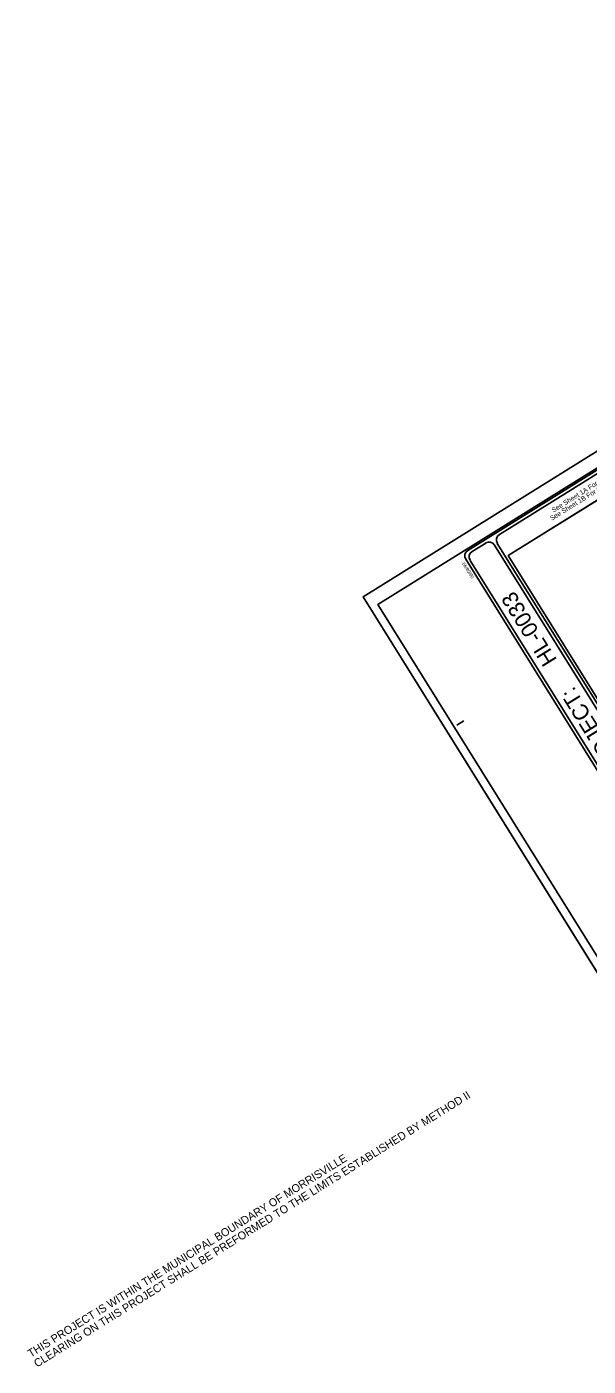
# Model space of a CAD drawing. Extents: x 2038094 to 2053858, y 751760 to 764312.
# Drawn here: x 2038094 to 2043353, y 751760 to 764312 of the extents above; entities that cross this region are included whole.
import ezdxf

# ---------------------------------------------------------------- set-up
doc = ezdxf.new("R2010")
doc.units = 0
for name, color, linetype in [('Sheet Clip Boundary CELL', 7, 'Continuous'), ('Sheet Cutting Line CELL', 7, 'Continuous'), ('Sheet Data Field CELL', 7, 'Continuous'), ('Sheet Plot Border Inside CELL', 7, 'Continuous'), ('Sheet Plot Border Outside CELL', 7, 'Continuous'), ('Sheet Title CELL', 7, 'Continuous')]:
    doc.layers.add(name, color=color, linetype=linetype)

msp = doc.modelspace()

# ---------------------------------------------------------------- linework, layer by layer
at = {"layer": 'Sheet Clip Boundary CELL'}
msp.add_lwpolyline([(2043662, 757657), (2046008, 759118), (2044949, 760817), (2042604, 759356)], close=True, dxfattribs=at)
at = {"layer": 'Sheet Cutting Line CELL'}
for q in [(2049821, 764312), (2044734, 753368)]:
    msp.add_line((2041244, 758970), q, dxfattribs=at)
at = {"layer": 'Sheet Plot Border Inside CELL'}
msp.add_lwpolyline([(2044729, 753524), (2053216, 758810), (2049869, 764184), (2041382, 758897)], close=True, dxfattribs=at)
at = {"layer": 'Sheet Plot Border Outside CELL'}
msp.add_lwpolyline([(2049821, 764312), (2041244, 758970), (2044734, 753368), (2053310, 758710)], close=True, dxfattribs=at)
at = {"layer": 'Sheet Title CELL'}
for p, q in [((2044949, 760817), (2042604, 759356)), ((2045712, 754260), (2042476, 759455)), ((2045151, 755218), (2042502, 759471)), ((2042124, 757769), (2042187, 757808)), ((2042124, 757769), (2042187, 757808))]:
    msp.add_line(p, q, dxfattribs=at)
for points in [[(2049762, 764099), (2042225, 759404)], [(2049753, 764058), (2042521, 759554)], [(2042394, 759474), (2042266, 759395)], [(2042206, 759322), (2045473, 754076)], [(2042206, 759322), (2045473, 754076)], [(2042247, 759312), (2045483, 754118)]]:
    msp.add_lwpolyline(points, dxfattribs=at)
for centre, start, end in [((2042553, 759503), 121.918, 211.918), ((2042425, 759424), 31.918, 121.918), ((2042257, 759354), 121.918, 211.918), ((2042298, 759344), 121.918, 211.918)]:
    msp.add_arc(centre, 60, start, end, dxfattribs=at)

# ---------------------------------------------------------------- texts
at = {"layer": 'Sheet Data Field CELL'}
for s, p in [('CLEARING ON THIS PROJECT SHALL BE PREFORMED TO THE LIMITS ESTABLISHED BY METHOD II', (2038190, 751746)), ('THIS PROJECT IS WITHIN THE MUNICIPAL BOUNDARY OF MORRISVILLE', (2038132, 751839))]:
    msp.add_text(s, height=75, rotation=31.918, dxfattribs=at).set_placement(p)
at = {"layer": 'Sheet Title CELL'}
for s, height, rotation, p in [('See Sheet 1B For Conventional Symbols', 45, 31.918, (2043012, 759682)), ('See Sheet 1A For Index of Sheets', 45, 31.918, (2043028, 759759)), ('09/08/99', 31.5, 121.918, (2042287, 759154)), ('HL-0033', 150, 121.918, (2043065, 758380)), ('TIP PROJECT:', 150, 121.918, (2043933, 756986))]:
    msp.add_text(s, height=height, rotation=rotation, dxfattribs=at).set_placement(p)

doc.saveas('drawing.dxf')
